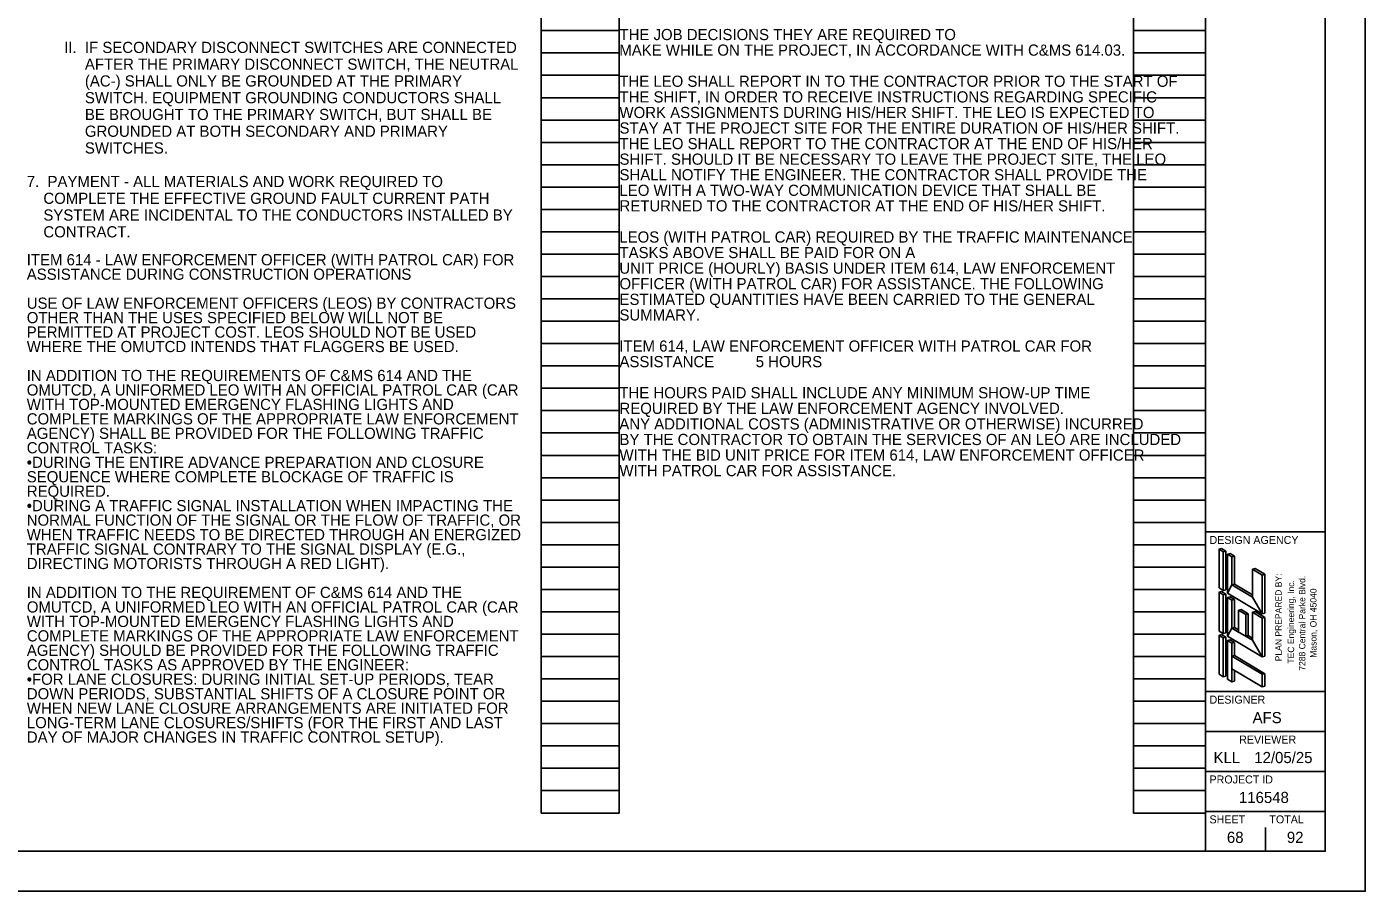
# Model space of a CAD drawing. Extents: x 0 to 34, y 0 to 22.
# Drawn here: x 17.24 to 34, y 0 to 10.83 of the extents above; entities that cross this region are included whole.
import ezdxf

# ---------------------------------------------------------------- set-up
doc = ezdxf.new("R2010")
doc.units = 0
for name, color, linetype in [('Default', 7, 'Continuous'), ('SH_Border', 7, 'Continuous'), ('SH_Cut_Line', 7, 'Continuous'), ('SH_Data', 7, 'Continuous'), ('SH_Text', 7, 'Continuous')]:
    doc.layers.add(name, color=color, linetype=linetype)

msp = doc.modelspace()

# ---------------------------------------------------------------- linework, layer by layer
at = {"layer": 'SH_Border'}
for p, q in [((32, 0.5), (32, 21.5)), ((32, 4.5), (33.5, 4.5)), ((32, 2.5), (33.5, 2.5)), ((32, 2), (33.5, 2)), ((32, 1.5), (33.5, 1.5)), ((32, 1), (33.5, 1))]:
    msp.add_line(p, q, dxfattribs=at)
msp.add_lwpolyline([(1.5, 21.5), (33.5, 21.5), (33.5, 0.5), (1.5, 0.5)], close=True, dxfattribs=at)
at = {"layer": 'SH_Cut_Line'}
msp.add_lwpolyline([(0, 0), (34, 0), (34, 22), (0, 22)], close=True, dxfattribs=at)
at = {"layer": 'SH_Data'}
for p, q in [((23.68, 0.98), (23.68, 21.14)), ((24.66, 0.98), (24.66, 21.14)), ((31.1, 0.98), (31.1, 21.14)), ((32, 0.98), (32, 21.14)), ((23.68, 10.78), (24.66, 10.78)), ((31.1, 10.78), (32, 10.78)), ((23.68, 10.5), (24.66, 10.5)), ((31.1, 10.5), (32, 10.5)), ((23.68, 10.22), (24.66, 10.22)), ((31.1, 10.22), (32, 10.22)), ((23.68, 9.94), (24.66, 9.94)), ((31.1, 9.94), (32, 9.94)), ((23.68, 9.66), (24.66, 9.66)), ((31.1, 9.66), (32, 9.66)), ((23.68, 9.38), (24.66, 9.38)), ((31.1, 9.38), (32, 9.38)), ((23.68, 9.1), (24.66, 9.1)), ((31.1, 9.1), (32, 9.1)), ((23.68, 8.82), (24.66, 8.82)), ((31.1, 8.82), (32, 8.82)), ((23.68, 8.54), (24.66, 8.54)), ((31.1, 8.54), (32, 8.54)), ((23.68, 8.26), (24.66, 8.26)), ((31.1, 8.26), (32, 8.26)), ((23.68, 7.98), (24.66, 7.98)), ((31.1, 7.98), (32, 7.98)), ((23.68, 7.7), (24.66, 7.7)), ((31.1, 7.7), (32, 7.7)), ((23.68, 7.42), (24.66, 7.42)), ((31.1, 7.42), (32, 7.42)), ((23.68, 7.14), (24.66, 7.14)), ((31.1, 7.14), (32, 7.14)), ((23.68, 6.86), (24.66, 6.86)), ((31.1, 6.86), (32, 6.86)), ((23.68, 6.58), (24.66, 6.58)), ((31.1, 6.58), (32, 6.58)), ((23.68, 6.3), (24.66, 6.3)), ((31.1, 6.3), (32, 6.3)), ((23.68, 6.02), (24.66, 6.02)), ((31.1, 6.02), (32, 6.02)), ((23.68, 5.74), (24.66, 5.74)), ((31.1, 5.74), (32, 5.74)), ((23.68, 5.46), (24.66, 5.46)), ((31.1, 5.46), (32, 5.46)), ((23.68, 5.18), (24.66, 5.18)), ((31.1, 5.18), (32, 5.18)), ((23.68, 4.9), (24.66, 4.9)), ((31.1, 4.9), (32, 4.9)), ((23.68, 4.62), (24.66, 4.62)), ((31.1, 4.62), (32, 4.62)), ((23.68, 4.34), (24.66, 4.34)), ((31.1, 4.34), (32, 4.34)), ((23.68, 4.06), (24.66, 4.06)), ((31.1, 4.06), (32, 4.06)), ((23.68, 3.78), (24.66, 3.78)), ((31.1, 3.78), (32, 3.78)), ((23.68, 3.5), (24.66, 3.5)), ((31.1, 3.5), (32, 3.5)), ((32.75, 3.5), (32.75, 3.5)), ((23.68, 3.22), (24.66, 3.22)), ((31.1, 3.22), (32, 3.22)), ((23.68, 2.94), (24.66, 2.94)), ((31.1, 2.94), (32, 2.94)), ((23.68, 2.66), (24.66, 2.66)), ((31.1, 2.66), (32, 2.66)), ((23.68, 2.38), (24.66, 2.38)), ((31.1, 2.38), (32, 2.38)), ((23.68, 2.1), (24.66, 2.1)), ((31.1, 2.1), (32, 2.1)), ((23.68, 1.82), (24.66, 1.82)), ((31.1, 1.82), (32, 1.82)), ((23.68, 1.54), (24.66, 1.54)), ((31.1, 1.54), (32, 1.54)), ((23.68, 1.26), (24.66, 1.26)), ((31.1, 1.26), (32, 1.26)), ((23.68, 0.98), (24.66, 0.98)), ((31.1, 0.98), (32, 0.98)), ((32.375, 0.675), (32.375, 0.675)), ((32.75, 0.5), (32.75, 0.8))]:
    msp.add_line(p, q, dxfattribs=at)
at = {"layer": 'SH_Text'}
for p, q in [((32.169, 4.285), (32.201, 4.294)), ((32.169, 3.799), (32.169, 4.285)), ((32.223, 4.253), (32.169, 4.285)), ((32.255, 4.261), (32.201, 4.294)), ((32.223, 4.253), (32.255, 4.261)), ((32.223, 3.767), (32.223, 4.253)), ((32.255, 3.775), (32.255, 4.261)), ((32.277, 4.221), (32.309, 4.229)), ((32.331, 4.188), (32.277, 4.221)), ((32.277, 3.735), (32.277, 4.221)), ((32.309, 4.229), (32.363, 4.196)), ((32.331, 4.188), (32.363, 4.196)), ((32.363, 4.196), (32.363, 3.845)), ((32.331, 3.837), (32.331, 4.188)), ((32.587, 4.034), (32.62, 4.042)), ((32.587, 3.683), (32.587, 4.034)), ((32.709, 3.961), (32.587, 4.034)), ((32.62, 4.042), (32.741, 3.97)), ((32.709, 3.961), (32.741, 3.97)), ((32.709, 3.475), (32.709, 3.961)), ((32.741, 3.97), (32.741, 3.484)), ((32.223, 3.767), (32.169, 3.799)), ((32.169, 3.745), (32.201, 3.754)), ((32.169, 3.259), (32.169, 3.745)), ((32.223, 3.713), (32.169, 3.745)), ((32.255, 3.722), (32.201, 3.754)), ((32.223, 3.767), (32.255, 3.775)), ((32.223, 3.713), (32.255, 3.722)), ((32.223, 3.227), (32.223, 3.713)), ((32.255, 3.236), (32.255, 3.722)), ((32.709, 3.475), (32.277, 3.735)), ((32.277, 3.681), (32.309, 3.689)), ((32.309, 3.689), (32.363, 3.656)), ((32.331, 3.837), (32.363, 3.845)), ((32.587, 3.683), (32.331, 3.837)), ((32.363, 3.845), (32.587, 3.711)), ((32.277, 3.195), (32.277, 3.681)), ((32.331, 3.648), (32.277, 3.681)), ((32.331, 3.648), (32.363, 3.656)), ((32.331, 3.297), (32.331, 3.648)), ((32.363, 3.656), (32.363, 3.305)), ((32.415, 3.519), (32.448, 3.527)), ((32.448, 3.527), (32.535, 3.474)), ((32.415, 3.519), (32.415, 3.247)), ((32.415, 3.519), (32.503, 3.466)), ((32.503, 3.466), (32.535, 3.474)), ((32.503, 3.466), (32.503, 3.194)), ((32.535, 3.474), (32.535, 3.202)), ((32.587, 3.494), (32.62, 3.502)), ((32.587, 3.143), (32.587, 3.494)), ((32.709, 3.421), (32.587, 3.494)), ((32.62, 3.502), (32.741, 3.43)), ((32.709, 3.475), (32.741, 3.484)), ((32.709, 3.421), (32.741, 3.43)), ((32.709, 2.935), (32.709, 3.421)), ((32.741, 3.43), (32.741, 2.944)), ((32.223, 3.227), (32.169, 3.259)), ((32.169, 3.205), (32.201, 3.215)), ((32.169, 2.719), (32.169, 3.205)), ((32.223, 3.173), (32.169, 3.205)), ((32.255, 3.181), (32.201, 3.215)), ((32.223, 3.227), (32.255, 3.236)), ((32.709, 2.935), (32.277, 3.195)), ((32.331, 3.297), (32.363, 3.305)), ((32.415, 3.247), (32.331, 3.297)), ((32.363, 3.305), (32.415, 3.274)), ((32.503, 3.194), (32.535, 3.202)), ((32.587, 3.143), (32.503, 3.194)), ((32.535, 3.202), (32.587, 3.171)), ((32.222, 3.173), (32.255, 3.181)), ((32.223, 2.687), (32.223, 3.173)), ((32.255, 2.695), (32.255, 3.181)), ((32.277, 3.141), (32.309, 3.151)), ((32.331, 3.108), (32.277, 3.141)), ((32.277, 2.655), (32.277, 3.141)), ((32.309, 3.151), (32.363, 3.116)), ((32.331, 3.108), (32.363, 3.116)), ((32.331, 2.944), (32.331, 3.108)), ((32.363, 3.116), (32.363, 2.952)), ((32.331, 2.944), (32.363, 2.952)), ((32.331, 2.944), (32.709, 2.717)), ((32.363, 2.952), (32.741, 2.725)), ((32.709, 2.935), (32.741, 2.944)), ((32.223, 2.687), (32.169, 2.719)), ((32.223, 2.687), (32.255, 2.695)), ((32.331, 2.787), (32.709, 2.56)), ((32.331, 2.622), (32.331, 2.787)), ((32.363, 2.63), (32.363, 2.767)), ((32.709, 2.717), (32.741, 2.725)), ((32.709, 2.56), (32.709, 2.717)), ((32.741, 2.725), (32.741, 2.568)), ((32.331, 2.622), (32.277, 2.655)), ((32.331, 2.622), (32.363, 2.63)), ((32.709, 2.56), (32.741, 2.568))]:
    msp.add_line(p, q, dxfattribs=at)
for points in [[(32.169, 3.799), (32.223, 3.767), (32.223, 4.253), (32.169, 4.285)], [(32.277, 3.735), (32.331, 3.837), (32.331, 4.188), (32.277, 4.221)], [(32.709, 3.475), (32.587, 3.683), (32.587, 4.034), (32.709, 3.961)], [(32.169, 3.259), (32.223, 3.227), (32.223, 3.713), (32.169, 3.745)], [(32.277, 3.735), (32.331, 3.837), (32.587, 3.683), (32.709, 3.475)], [(32.277, 3.195), (32.331, 3.297), (32.331, 3.648), (32.277, 3.681)], [(32.415, 3.247), (32.415, 3.519), (32.503, 3.466), (32.503, 3.194)], [(32.709, 2.935), (32.587, 3.143), (32.587, 3.494), (32.709, 3.421)], [(32.169, 2.719), (32.223, 2.687), (32.223, 3.173), (32.169, 3.205)], [(32.277, 3.195), (32.331, 3.297), (32.587, 3.143), (32.709, 2.935)], [(32.277, 2.655), (32.331, 2.622), (32.331, 3.108), (32.277, 3.141)], [(32.331, 2.787), (32.331, 2.944), (32.709, 2.717), (32.709, 2.56)]]:
    msp.add_lwpolyline(points, close=True, dxfattribs=at)

# ---------------------------------------------------------------- texts
at = {"layer": 'Default'}
for s, p in [('PLAN PREPARED BY:', (32.954, 2.88)), ('TEC Engineering, Inc.', (33.11, 2.851)), ('7288 Central Parke Blvd.', (33.25, 2.762)), ('Mason, OH 45040', (33.39, 2.925))]:
    msp.add_text(s, height=0.08, rotation=90, dxfattribs=at).set_placement(p)
at = {"layer": 'SH_Data'}
for s, height, p in [('DESIGN AGENCY', 0.1, (32.05, 4.35)), ('DESIGNER', 0.1, (32.05, 2.35)), ('AFS', 0.14, (32.59, 2.105)), ('REVIEWER', 0.1, (32.422, 1.85)), ('KLL', 0.14, (32.101, 1.605)), ('12/05/25', 0.14, (32.611, 1.605)), ('PROJECT ID', 0.1, (32.05, 1.35)), ('116548', 0.14, (32.419, 1.105)), ('SHEET', 0.1, (32.05, 0.85)), ('TOTAL', 0.1, (32.8, 0.85)), ('68', 0.14, (32.268, 0.605)), ('92', 0.14, (33.019, 0.605))]:
    msp.add_text(s, height=height, dxfattribs=at).set_placement(p)
at = {"layer": 'SH_Text'}
for s, p in [('THE JOB DECISIONS THEY ARE REQUIRED TO', (24.662, 10.661)), ('         II.  IF SECONDARY DISCONNECT SWITCHES ARE CONNECTED', (17.24, 10.5)), ('MAKE WHILE ON THE PROJECT, IN ACCORDANCE WITH C&MS 614.03.', (24.66, 10.466)), ('              AFTER THE PRIMARY DISCONNECT SWITCH, THE NEUTRAL', (17.24, 10.29)), ('              (AC-) SHALL ONLY BE GROUNDED AT THE PRIMARY', (17.24, 10.08)), ('THE LEO SHALL REPORT IN TO THE CONTRACTOR PRIOR TO THE START OF ', (24.66, 10.076)), ('              SWITCH. EQUIPMENT GROUNDING CONDUCTORS SHALL', (17.24, 9.87)), ('THE SHIFT, IN ORDER TO RECEIVE INSTRUCTIONS REGARDING SPECIFIC ', (24.662, 9.88)), ('              BE BROUGHT TO THE PRIMARY SWITCH, BUT SHALL BE', (17.24, 9.66)), ('WORK ASSIGNMENTS DURING HIS/HER SHIFT. THE LEO IS EXPECTED TO ', (24.662, 9.685)), ('              GROUNDED AT BOTH SECONDARY AND PRIMARY', (17.24, 9.45)), ('STAY AT THE PROJECT SITE FOR THE ENTIRE DURATION OF HIS/HER SHIFT. ', (24.662, 9.49)), ('THE LEO SHALL REPORT TO THE CONTRACTOR AT THE END OF HIS/HER ', (24.662, 9.295)), ('              SWITCHES.', (17.24, 9.24)), ('SHIFT. SHOULD IT BE NECESSARY TO LEAVE THE PROJECT SITE, THE LEO ', (24.662, 9.1)), ('7.  PAYMENT - ALL MATERIALS AND WORK REQUIRED TO', (17.24, 8.82)), ('SHALL NOTIFY THE ENGINEER. THE CONTRACTOR SHALL PROVIDE THE ', (24.662, 8.905)), ('    COMPLETE THE EFFECTIVE GROUND FAULT CURRENT PATH', (17.24, 8.61)), ('LEO WITH A TWO-WAY COMMUNICATION DEVICE THAT SHALL BE ', (24.662, 8.71)), ('RETURNED TO THE CONTRACTOR AT THE END OF HIS/HER SHIFT. ', (24.662, 8.515)), ('    SYSTEM ARE INCIDENTAL TO THE CONDUCTORS INSTALLED BY', (17.24, 8.4)), ('    CONTRACT.', (17.24, 8.19)), ('LEOS (WITH PATROL CAR) REQUIRED BY THE TRAFFIC MAINTENANCE ', (24.66, 8.125)), ('TASKS ABOVE SHALL BE PAID FOR ON A', (24.662, 7.93)), ('ITEM 614 - LAW ENFORCEMENT OFFICER (WITH PATROL CAR) FOR ', (17.24, 7.84)), ('UNIT PRICE (HOURLY) BASIS UNDER ITEM 614, LAW ENFORCEMENT ', (24.66, 7.735)), ('ASSISTANCE DURING CONSTRUCTION OPERATIONS', (17.24, 7.659)), ('OFFICER (WITH PATROL CAR) FOR ASSISTANCE. THE FOLLOWING ', (24.662, 7.54)), ('USE OF LAW ENFORCEMENT OFFICERS (LEOS) BY CONTRACTORS ', (17.24, 7.296)), ('ESTIMATED QUANTITIES HAVE BEEN CARRIED TO THE GENERAL ', (24.662, 7.344)), ('OTHER THAN THE USES SPECIFIED BELOW WILL NOT BE ', (17.24, 7.115)), ('SUMMARY.', (24.662, 7.149)), ('PERMITTED AT PROJECT COST. LEOS SHOULD NOT BE USED ', (17.24, 6.934)), ('WHERE THE OMUTCD INTENDS THAT FLAGGERS BE USED.', (17.24, 6.753)), ('ITEM 614, LAW ENFORCEMENT OFFICER WITH PATROL CAR FOR ', (24.66, 6.759)), ('ASSISTANCE          5 HOURS', (24.662, 6.564)), ('IN ADDITION TO THE REQUIREMENTS OF C&MS 614 AND THE ', (17.24, 6.39)), ('OMUTCD, A UNIFORMED LEO WITH AN OFFICIAL PATROL CAR (CAR ', (17.24, 6.209)), ('THE HOURS PAID SHALL INCLUDE ANY MINIMUM SHOW-UP TIME ', (24.66, 6.174)), ('WITH TOP-MOUNTED EMERGENCY FLASHING LIGHTS AND ', (17.24, 6.028)), ('REQUIRED BY THE LAW ENFORCEMENT AGENCY INVOLVED.', (24.662, 5.979)), ('COMPLETE MARKINGS OF THE APPROPRIATE LAW ENFORCEMENT ', (17.24, 5.847)), ('ANY ADDITIONAL COSTS (ADMINISTRATIVE OR OTHERWISE) INCURRED ', (24.66, 5.784)), ('AGENCY) SHALL BE PROVIDED FOR THE FOLLOWING TRAFFIC ', (17.24, 5.666)), ('BY THE CONTRACTOR TO OBTAIN THE SERVICES OF AN LEO ARE INCLUDED ', (24.662, 5.589)), ('CONTROL TASKS:', (17.24, 5.485)), ('WITH THE BID UNIT PRICE FOR ITEM 614, LAW ENFORCEMENT OFFICER ', (24.662, 5.394)), ('•DURING THE ENTIRE ADVANCE PREPARATION AND CLOSURE ', (17.24, 5.303)), ('SEQUENCE WHERE COMPLETE BLOCKAGE OF TRAFFIC IS ', (17.24, 5.122)), ('WITH PATROL CAR FOR ASSISTANCE.', (24.662, 5.199)), ('REQUIRED.', (17.241, 4.941)), ('•DURING A TRAFFIC SIGNAL INSTALLATION WHEN IMPACTING THE ', (17.24, 4.76)), ('NORMAL FUNCTION OF THE SIGNAL OR THE FLOW OF TRAFFIC, OR ', (17.24, 4.579)), ('WHEN TRAFFIC NEEDS TO BE DIRECTED THROUGH AN ENERGIZED ', (17.24, 4.397)), ('TRAFFIC SIGNAL CONTRARY TO THE SIGNAL DISPLAY (E.G., ', (17.24, 4.216)), ('DIRECTING MOTORISTS THROUGH A RED LIGHT).', (17.241, 4.035)), ('IN ADDITION TO THE REQUIREMENT OF C&MS 614 AND THE ', (17.24, 3.673)), ('OMUTCD, A UNIFORMED LEO WITH AN OFFICIAL PATROL CAR (CAR ', (17.241, 3.491)), ('WITH TOP-MOUNTED EMERGENCY FLASHING LIGHTS AND ', (17.241, 3.31)), ('COMPLETE MARKINGS OF THE APPROPRIATE LAW ENFORCEMENT ', (17.241, 3.129)), ('AGENCY) SHOULD BE PROVIDED FOR THE FOLLOWING TRAFFIC ', (17.241, 2.948)), ('CONTROL TASKS AS APPROVED BY THE ENGINEER:', (17.241, 2.767)), ('•FOR LANE CLOSURES: DURING INITIAL SET-UP PERIODS, TEAR ', (17.24, 2.586)), ('DOWN PERIODS, SUBSTANTIAL SHIFTS OF A CLOSURE POINT OR ', (17.241, 2.404)), ('WHEN NEW LANE CLOSURE ARRANGEMENTS ARE INITIATED FOR ', (17.241, 2.223)), ('LONG-TERM LANE CLOSURES/SHIFTS (FOR THE FIRST AND LAST ', (17.241, 2.042)), ('DAY OF MAJOR CHANGES IN TRAFFIC CONTROL SETUP).', (17.241, 1.861))]:
    msp.add_text(s, height=0.14, dxfattribs=at).set_placement(p)

doc.saveas('drawing.dxf')
